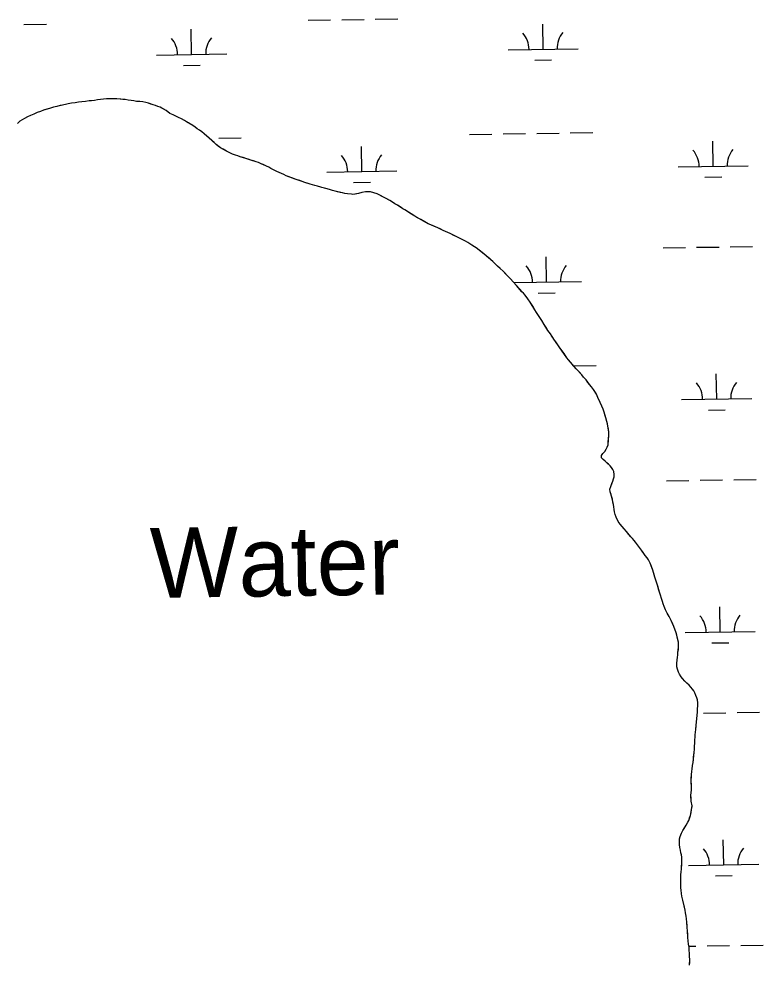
# Model space of a CAD drawing. Extents: x 3807117 to 3845308, y 337856 to 363736.
# Drawn here: x 3839396 to 3840459, y 351307 to 352657 of the extents above; entities that cross this region are included whole.
import ezdxf

# ---------------------------------------------------------------- set-up
doc = ezdxf.new("R2010")
doc.units = 0
for name, color, linetype in [('V-RIVR-IDEN', 7, 'Continuous'), ('V-TOPO-SHOR', 7, 'Continuous'), ('V-WETL-SWMP', 7, 'Continuous')]:
    doc.layers.add(name, color=color, linetype=linetype)

msp = doc.modelspace()

# ---------------------------------------------------------------- linework, layer by layer
at = {"layer": 'V-TOPO-SHOR'}
for points in [[(3839581.4, 352536.2), (3839577.6, 352537.3), (3839573.1, 352538.3), (3839569, 352538.6), (3839563.9, 352538.8), (3839560.5, 352539.5), (3839556.4, 352540.1), (3839552.1, 352540.8), (3839548.1, 352541.4), (3839544.6, 352541.7), (3839540.6, 352542.1), (3839535.9, 352542.6), (3839531, 352542.6), (3839525.9, 352542.7), (3839521.2, 352542.5), (3839516.9, 352542.1), (3839512.7, 352541.4), (3839508.6, 352541), (3839504.1, 352540.2), (3839499.8, 352539.8), (3839496.4, 352539.5), (3839491.3, 352538.9), (3839486.2, 352538.4), (3839481.5, 352537.8), (3839476.6, 352537), (3839471.5, 352536.4), (3839466.4, 352535.3), (3839462.7, 352534.5), (3839458.2, 352533.5), (3839455.2, 352532.9), (3839450.5, 352531.8), (3839445.8, 352530.6), (3839439.9, 352528.8), (3839436.2, 352527.8), (3839431.5, 352526.4), (3839426.8, 352524.5), (3839422.1, 352522.9), (3839417.4, 352520.9), (3839412.7, 352518.7), (3839408.6, 352517.1), (3839404.3, 352514.5), (3839400.9, 352512.7), (3839397.6, 352510.5), (3839394.1, 352507.3)], [(3839933.3, 352392.7), (3839929.7, 352395.1), (3839925.7, 352397.3), (3839921.5, 352399.7), (3839918.8, 352401.3), (3839915.1, 352403.2), (3839910.5, 352405.6), (3839907.6, 352406.9), (3839902.9, 352408.4), (3839898.3, 352409.5), (3839894.3, 352409.9), (3839891.1, 352409.6), (3839885.8, 352408.6), (3839881.2, 352407.3), (3839876.2, 352406.4), (3839873, 352405.9), (3839871.2, 352406.3), (3839865.5, 352406.8), (3839861.7, 352407.4), (3839858.4, 352408.1), (3839855.2, 352408.9), (3839851.3, 352409.9), (3839847.9, 352410.6), (3839844.2, 352411.6), (3839839.8, 352412.9), (3839836.5, 352413.8), (3839832.4, 352415), (3839829, 352416.1), (3839826, 352416.9), (3839822.5, 352417.8), (3839819, 352419), (3839815.6, 352419.9), (3839812.1, 352420.9), (3839807.9, 352422.2), (3839807.5, 352422.2), (3839804.4, 352423.2), (3839800.8, 352424.5), (3839797.5, 352425.7), (3839793.7, 352427), (3839790.8, 352428), (3839787.6, 352429.1), (3839784.6, 352430.3), (3839780.9, 352431.6), (3839777.7, 352432.8), (3839774.6, 352434.3), (3839771.2, 352435.7), (3839768.1, 352437.2), (3839764.7, 352438.9), (3839761.7, 352440.3), (3839759, 352441.8), (3839756.2, 352443.2), (3839752.9, 352445.1), (3839748.9, 352446.9), (3839745.2, 352448.6), (3839742, 352449.9), (3839738.4, 352451.7), (3839735.1, 352452.8), (3839731.3, 352454), (3839727.4, 352455.1), (3839723.5, 352456.5), (3839720.5, 352457.4), (3839716.6, 352458.6), (3839712.4, 352459.7), (3839708.9, 352461.1), (3839705.5, 352462), (3839701.2, 352463.7), (3839697.4, 352465.3), (3839692.5, 352467.8), (3839688, 352470.5), (3839684, 352472.8), (3839680.8, 352475.1), (3839677.9, 352477.5), (3839674.9, 352480.2), (3839671.7, 352483.1), (3839668.1, 352486.2), (3839664.4, 352489.3), (3839660.6, 352492.5), (3839657.3, 352495.4), (3839654.1, 352497.7), (3839650.7, 352499.8), (3839647.8, 352502), (3839644.6, 352504.7), (3839641.4, 352506.4), (3839638.3, 352508.2), (3839635.3, 352509.7), (3839632.5, 352511.5), (3839628.2, 352514), (3839624, 352515.9), (3839620.1, 352518), (3839616.3, 352519.8), (3839611.8, 352521.7), (3839609.2, 352523.6), (3839606.3, 352525.8), (3839603.1, 352527.7), (3839600.5, 352529.3), (3839597.8, 352530.6), (3839594.4, 352531.8), (3839591.4, 352532.9), (3839588.1, 352533.9), (3839584.7, 352535), (3839581.4, 352536.2)], [(3840230, 352036), (3840232.8, 352039), (3840235.1, 352042.1), (3840236.4, 352045.1), (3840237.6, 352048.5), (3840237.9, 352052.8), (3840238.3, 352057.5), (3840238.6, 352061.8), (3840238.8, 352066.6), (3840238.2, 352070.7), (3840237.5, 352074.8), (3840236.7, 352078.3), (3840235.7, 352081.5), (3840234.5, 352086.8), (3840233.1, 352091.3), (3840231.9, 352095.2), (3840230.4, 352099.1), (3840228.6, 352103.6), (3840226.4, 352108.9), (3840225, 352111.8), (3840223.2, 352115.8), (3840221.2, 352120.5), (3840219.6, 352123), (3840216.8, 352127.3), (3840214, 352131.2), (3840211.1, 352134.7), (3840208.9, 352137.4), (3840206.1, 352141), (3840202.3, 352145.2), (3840199.9, 352148.2), (3840196.1, 352152.5), (3840192.2, 352157.1), (3840188.4, 352161.4), (3840184.2, 352166.1), (3840181.1, 352169.8), (3840178.9, 352172.8), (3840174.7, 352178.8), (3840171.9, 352182.7), (3840168.9, 352187), (3840166.9, 352189.6), (3840163.9, 352193.9), (3840160.1, 352199.1), (3840158.5, 352201.7), (3840156.8, 352204.2), (3840155.2, 352206.7), (3840151.6, 352211.8), (3840150, 352214.4), (3840146.4, 352220.2), (3840143, 352226.1), (3840139.4, 352231.6), (3840135.6, 352237.6), (3840133.2, 352241.1), (3840130, 352246.2), (3840126.4, 352251.9), (3840123.1, 352257), (3840119.3, 352261.9), (3840116.7, 352264.8), (3840114.5, 352267.1), (3840111.7, 352270.2), (3840107, 352275.7), (3840102.2, 352281), (3840098.4, 352285.3), (3840095.8, 352287.8), (3840091.7, 352292.1), (3840087.7, 352296.2), (3840083.7, 352300.1), (3840079.8, 352303.4), (3840077.6, 352305.6), (3840072.8, 352310.1), (3840068.6, 352313.8), (3840063.6, 352318.3), (3840060.7, 352320.9), (3840055.2, 352325), (3840049.3, 352329.6), (3840046.8, 352331.4), (3840043.1, 352333.7), (3840037.2, 352337.2), (3840034, 352339.1), (3840029.2, 352341.6), (3840025.4, 352343.7), (3840020.6, 352346), (3840017.5, 352347.5), (3840011.9, 352350.3), (3840005.2, 352353.2), (3840002.3, 352354.7), (3839997.6, 352356.7), (3839994.3, 352358.1), (3839989.7, 352360.2), (3839984.3, 352362.7), (3839980.8, 352364.2), (3839975.7, 352367), (3839970.1, 352370.1), (3839964.7, 352373.1), (3839961.6, 352374.8), (3839956.9, 352377.8), (3839951.6, 352381.1), (3839947.4, 352383.8), (3839944.5, 352385.5), (3839940.5, 352388.1), (3839936.9, 352390.5), (3839933.3, 352392.7)], [(3840365.3, 351667.1), (3840365.3, 351671), (3840365.6, 351675.7), (3840365.6, 351679.8), (3840365.1, 351684), (3840364.3, 351687.1), (3840363.1, 351690.4), (3840361.5, 351694.1), (3840359.9, 351696.7), (3840358.1, 351699.2), (3840355.7, 351702), (3840353.4, 351704.9), (3840350.2, 351708), (3840347.4, 351710.9), (3840344, 351714.6), (3840342, 351717), (3840339.6, 351720.9), (3840338.2, 351723.8), (3840336.8, 351727.9), (3840336, 351731.3), (3840335.8, 351736.6), (3840336.1, 351740.5), (3840336.7, 351745), (3840337.2, 351748), (3840337.4, 351751.5), (3840338, 351755.5), (3840338.3, 351758.8), (3840338.3, 351763.3), (3840338.1, 351766.5), (3840336.8, 351771.8), (3840335.8, 351776.5), (3840335, 351779.6), (3840333.4, 351783.7), (3840331.4, 351789), (3840329, 351794.3), (3840327.6, 351797.4), (3840324.7, 351802.9), (3840321.8, 351808), (3840319.5, 351812.7), (3840317.7, 351817.6), (3840316.1, 351821.3), (3840315.3, 351824.3), (3840313.7, 351829), (3840312.5, 351833.7), (3840311.1, 351838), (3840309.8, 351842.3), (3840308.6, 351846.4), (3840307.2, 351850.7), (3840305.8, 351855), (3840304.6, 351859.4), (3840303, 351864.5), (3840301.3, 351869.5), (3840299.5, 351874.4), (3840297.5, 351879.5), (3840295.3, 351884.2), (3840293.5, 351886.8), (3840290.7, 351890.3), (3840287.7, 351894.4), (3840285.2, 351897.9), (3840282.6, 351901.6), (3840279.6, 351905.5), (3840276.8, 351909.2), (3840274.8, 351911.6), (3840272.4, 351914.7), (3840270.2, 351917), (3840266.9, 351920.9), (3840263.7, 351924.6), (3840260.5, 351928.5), (3840257.5, 351931.9), (3840254.9, 351934.8), (3840252.2, 351938.9), (3840250.7, 351941.8), (3840249.3, 351945), (3840247.7, 351948.9), (3840246.7, 351952.6), (3840246.3, 351956.3), (3840245.9, 351959.5), (3840245.4, 351963), (3840244.6, 351966.3), (3840243.8, 351970.5), (3840243, 351973.8), (3840242, 351977.3), (3840240.8, 351981.4), (3840240.3, 351985), (3840241.7, 351988.9), (3840243.2, 351992.9), (3840244.6, 351996.2), (3840245.5, 351999.6), (3840246.1, 352002.7), (3840246.2, 352005.9), (3840245.6, 352010), (3840244.2, 352013.3), (3840242.6, 352015.9), (3840240.4, 352018.2), (3840238, 352020.5), (3840235.9, 352022.7), (3840233.3, 352025), (3840230.7, 352027.2), (3840228.1, 352029.7), (3840228.1, 352033.2), (3840230, 352036)], [(3840354, 351305.2), (3840354.2, 351308.8), (3840354.4, 351313.1), (3840353.9, 351317.4), (3840353.7, 351321.9), (3840353.5, 351326.3), (3840353.2, 351330.8), (3840352.6, 351335.1), (3840352.1, 351340), (3840351.5, 351344.7), (3840351.3, 351349.2), (3840351, 351354), (3840350.6, 351358.7), (3840350.4, 351361.8), (3840350.1, 351366.5), (3840349.7, 351371.4), (3840349.3, 351375), (3840348.4, 351379.7), (3840347.6, 351383.6), (3840346.6, 351387.7), (3840345.6, 351392.2), (3840344.2, 351398.1), (3840343.1, 351403.4), (3840342.5, 351407.3), (3840341.9, 351412.3), (3840341.6, 351415.4), (3840341.6, 351421.5), (3840341.5, 351425.8), (3840341.7, 351430.5), (3840341.7, 351433.7), (3840342, 351438.6), (3840342.4, 351441.8), (3840342.7, 351446.1), (3840343.1, 351450.2), (3840343.1, 351454.3), (3840342.8, 351459.1), (3840342.4, 351462.4), (3840341.6, 351465.3), (3840341, 351469.1), (3840339.9, 351473.2), (3840339.5, 351477.5), (3840339.5, 351481.4), (3840339.8, 351485.6), (3840340.4, 351488.9), (3840342.3, 351493.6), (3840344.6, 351497.6), (3840346.4, 351500.4), (3840349.3, 351504.9), (3840351.6, 351509.1), (3840352.9, 351511.8), (3840354.1, 351515.4), (3840355.2, 351518.7), (3840356.2, 351523.3), (3840356.9, 351527.2), (3840357.5, 351531.3), (3840357.7, 351532.7), (3840356.4, 351539.2), (3840356.2, 351544.1), (3840356, 351547.4), (3840356.3, 351551.4), (3840356.7, 351555.5), (3840356.8, 351559.2), (3840356.6, 351564), (3840356.4, 351567.1), (3840356.5, 351571.6), (3840356.7, 351576.7), (3840357.2, 351582.1), (3840357.8, 351585), (3840358.3, 351590.1), (3840359.1, 351594.3), (3840359.4, 351598.2), (3840359.8, 351602.3), (3840360.2, 351605.7), (3840360.5, 351609.4), (3840361.1, 351613), (3840361.2, 351617.3), (3840361.4, 351622.6), (3840361.5, 351626.7), (3840361.9, 351630.7), (3840362.1, 351634.2), (3840362.4, 351638.1), (3840362.8, 351641.9), (3840363.5, 351647.8), (3840364.1, 351652.7), (3840364.4, 351656.8), (3840365, 351661.7), (3840365.3, 351667.1)]]:
    msp.add_lwpolyline(points, dxfattribs=at)
at = {"layer": 'V-WETL-SWMP'}
for p, q in [((3839403.4, 352648.8), (3839435.4, 352649.2)), ((3839809.2, 352654.9), (3839841.2, 352655.3)), ((3839857.2, 352655.6), (3839889.2, 352656)), ((3839905.2, 352656.3), (3839937.2, 352656.8)), ((3840144.7, 352613.4), (3840144.2, 352649.4)), ((3839642.9, 352605.9), (3839642.3, 352641.9)), ((3840094.7, 352612.7), (3840194.7, 352614.2)), ((3839592.9, 352605.2), (3839692.9, 352606.7)), ((3840133, 352597.8), (3840157, 352598.2)), ((3839631.1, 352590.3), (3839655.1, 352590.7)), ((3839681.8, 352486.4), (3839713.8, 352486.9)), ((3840039.7, 352491.8), (3840071.7, 352492.3)), ((3840087.7, 352492.5), (3840119.7, 352493)), ((3840135.7, 352493.2), (3840167.7, 352493.7)), ((3840183.7, 352493.9), (3840215.7, 352494.4)), ((3839885.9, 352438.7), (3839885.3, 352474.7)), ((3840387.7, 352446.2), (3840387.2, 352482.2)), ((3840337.7, 352445.5), (3840437.7, 352447)), ((3839835.9, 352438), (3839935.9, 352439.5)), ((3839874.1, 352423.1), (3839898.1, 352423.5)), ((3840376, 352430.6), (3840400, 352431)), ((3840316.1, 352329.7), (3840348.1, 352330.2)), ((3840364.1, 352330.5), (3840396.1, 352330.9)), ((3840412.1, 352331.2), (3840444, 352331.6)), ((3840149.7, 352280.8), (3840149.2, 352316.8)), ((3840103, 352280.1), (3840199.7, 352281.6)), ((3840137.9, 352265.2), (3840161.9, 352265.6)), ((3840188.7, 352161.3), (3840220.7, 352161.8)), ((3840392.7, 352113.6), (3840392.2, 352149.6)), ((3840342.7, 352112.9), (3840442.7, 352114.4)), ((3840380.9, 352098), (3840404.9, 352098.4)), ((3840321, 351997.1), (3840353, 351997.6)), ((3840369, 351997.8), (3840401, 351998.3)), ((3840417, 351998.5), (3840449, 351999)), ((3840397.7, 351781), (3840397.2, 351817)), ((3840347.7, 351780.2), (3840447.7, 351781.7)), ((3840385.9, 351765.4), (3840409.9, 351765.7)), ((3840374, 351665.2), (3840406, 351665.7)), ((3840422, 351665.9), (3840454, 351666.4)), ((3840402.7, 351448.3), (3840402.1, 351484.3)), ((3840352.7, 351447.6), (3840452.7, 351449.1)), ((3840390.9, 351432.7), (3840414.9, 351433.1)), ((3840353, 351332.1), (3840363, 351332.3)), ((3840379, 351332.5), (3840411, 351333)), ((3840427, 351333.3), (3840459, 351333.7))]:
    msp.add_line(p, q, dxfattribs=at)
for points in [[(3839581.4, 352536.2), (3839577.6, 352537.3), (3839573.1, 352538.3), (3839569, 352538.6), (3839563.9, 352538.8), (3839560.5, 352539.5), (3839556.4, 352540.1), (3839552.1, 352540.8), (3839548.1, 352541.4), (3839535.9, 352542.6), (3839531, 352542.6), (3839525.9, 352542.7), (3839521.2, 352542.5), (3839516.9, 352542.1), (3839512.7, 352541.4), (3839508.6, 352541), (3839504.1, 352540.2), (3839496.4, 352539.5), (3839491.3, 352538.9), (3839486.2, 352538.4), (3839481.5, 352537.8), (3839476.6, 352537), (3839471.5, 352536.4), (3839466.4, 352535.3), (3839450.5, 352531.8), (3839445.8, 352530.6), (3839439.9, 352528.8), (3839431.5, 352526.4), (3839426.8, 352524.5), (3839422.1, 352522.9), (3839417.4, 352520.9), (3839412.7, 352518.7), (3839408.6, 352517.1), (3839404.3, 352514.5), (3839400.9, 352512.7), (3839397.6, 352510.5), (3839394.1, 352507.3)], [(3840135.6, 352237.6), (3840133.2, 352241.1), (3840126.4, 352251.9), (3840123.1, 352257), (3840119.3, 352261.9), (3840098.4, 352285.3), (3840095.8, 352287.8), (3840087.7, 352296.2), (3840083.7, 352300.1), (3840079.8, 352303.4), (3840077.6, 352305.6), (3840072.8, 352310.1), (3840060.7, 352320.9), (3840049.3, 352329.6), (3840046.8, 352331.4), (3840043.1, 352333.7), (3840037.2, 352337.2), (3840034, 352339.1), (3840025.4, 352343.7), (3840020.6, 352346), (3840011.9, 352350.3), (3840005.2, 352353.2), (3840002.3, 352354.7), (3839994.3, 352358.1), (3839984.3, 352362.7), (3839980.8, 352364.2), (3839961.6, 352374.8), (3839947.4, 352383.8), (3839944.5, 352385.5), (3839936.9, 352390.5), (3839933.3, 352392.7), (3839929.7, 352395.1), (3839925.7, 352397.3), (3839918.8, 352401.3), (3839910.5, 352405.6), (3839907.6, 352406.9), (3839902.9, 352408.4), (3839898.3, 352409.5), (3839894.3, 352409.9), (3839891.1, 352409.6), (3839885.8, 352408.6), (3839881.2, 352407.3), (3839873, 352405.9), (3839871.2, 352406.3), (3839865.5, 352406.8), (3839861.7, 352407.4), (3839844.2, 352411.6), (3839839.8, 352412.9), (3839832.4, 352415), (3839829, 352416.1), (3839822.5, 352417.8), (3839819, 352419), (3839812.1, 352420.9), (3839807.9, 352422.2), (3839807.5, 352422.2), (3839804.4, 352423.2), (3839800.8, 352424.5), (3839790.8, 352428), (3839777.7, 352432.8), (3839774.6, 352434.3), (3839771.2, 352435.7), (3839764.7, 352438.9), (3839761.7, 352440.3), (3839759, 352441.8), (3839756.2, 352443.2), (3839752.9, 352445.1), (3839742, 352449.9), (3839738.4, 352451.7), (3839735.1, 352452.8), (3839727.4, 352455.1), (3839720.5, 352457.4), (3839712.4, 352459.7), (3839708.9, 352461), (3839705.5, 352462), (3839701.2, 352463.7), (3839697.4, 352465.3), (3839692.5, 352467.8), (3839684, 352472.8), (3839677.9, 352477.5), (3839671.7, 352483.1), (3839668.1, 352486.2), (3839660.6, 352492.5), (3839657.3, 352495.4), (3839654.1, 352497.7), (3839650.7, 352499.8), (3839647.8, 352502), (3839644.6, 352504.7), (3839635.3, 352509.7), (3839632.5, 352511.5), (3839628.2, 352514), (3839624, 352515.9), (3839620.1, 352518), (3839616.3, 352519.8), (3839611.8, 352521.7), (3839606.3, 352525.8), (3839600.5, 352529.3), (3839597.8, 352530.6), (3839594.4, 352531.8), (3839591.4, 352532.9), (3839588.1, 352533.9), (3839581.4, 352536.2)], [(3840347.4, 351710.9), (3840344, 351714.6), (3840342, 351717), (3840339.6, 351720.9), (3840338.2, 351723.8), (3840336.8, 351727.9), (3840336, 351731.3), (3840335.8, 351736.6), (3840336.1, 351740.5), (3840336.7, 351745), (3840337.2, 351748), (3840337.4, 351751.5), (3840338.3, 351758.8), (3840338.3, 351763.3), (3840338.1, 351766.5), (3840335.8, 351776.5), (3840335, 351779.6), (3840331.4, 351789), (3840327.6, 351797.4), (3840324.7, 351802.9), (3840321.8, 351808), (3840319.5, 351812.7), (3840317.7, 351817.6), (3840316.1, 351821.3), (3840315.3, 351824.3), (3840313.7, 351829), (3840312.5, 351833.7), (3840311.1, 351838), (3840308.6, 351846.4), (3840305.8, 351855), (3840304.6, 351859.4), (3840301.3, 351869.5), (3840297.5, 351879.5), (3840295.3, 351884.2), (3840293.5, 351886.8), (3840290.7, 351890.3), (3840285.2, 351897.9), (3840282.6, 351901.6), (3840276.8, 351909.2), (3840274.8, 351911.6), (3840272.4, 351914.7), (3840270.2, 351917), (3840263.7, 351924.6), (3840260.5, 351928.5), (3840254.9, 351934.8), (3840252.2, 351938.9), (3840249.3, 351945), (3840247.7, 351948.9), (3840246.7, 351952.6), (3840245.4, 351963), (3840243, 351973.8), (3840240.8, 351981.4), (3840240.3, 351985), (3840241.7, 351988.9), (3840244.6, 351996.2), (3840245.5, 351999.6), (3840246.1, 352002.7), (3840246.2, 352005.9), (3840245.6, 352010), (3840244.2, 352013.3), (3840242.6, 352015.9), (3840240.4, 352018.2), (3840235.9, 352022.7), (3840233.3, 352025), (3840230.7, 352027.2), (3840228.1, 352029.7), (3840228.1, 352033.2), (3840230, 352036), (3840232.8, 352039), (3840235.1, 352042.1), (3840236.4, 352045.1), (3840237.6, 352048.5), (3840238.6, 352061.8), (3840238.8, 352066.6), (3840237.5, 352074.8), (3840236.7, 352078.3), (3840235.7, 352081.5), (3840234.5, 352086.8), (3840231.9, 352095.2), (3840230.4, 352099.1), (3840226.4, 352108.9), (3840223.2, 352115.8), (3840221.2, 352120.5), (3840216.8, 352127.3), (3840214, 352131.2), (3840211.1, 352134.7), (3840206.1, 352141), (3840202.3, 352145.2), (3840199.9, 352148.2), (3840192.2, 352157.1), (3840181.1, 352169.8), (3840178.9, 352172.8), (3840168.9, 352187), (3840166.9, 352189.6), (3840160.1, 352199.1), (3840155.2, 352206.7), (3840151.6, 352211.8), (3840146.4, 352220.2), (3840143, 352226.1), (3840139.4, 352231.6), (3840135.6, 352237.6)], [(3840354, 351305.2), (3840354.4, 351313.1), (3840353.9, 351317.4), (3840353.2, 351330.8), (3840352.6, 351335.1), (3840352.1, 351340), (3840351.5, 351344.7), (3840351, 351354), (3840350.6, 351358.7), (3840350.1, 351366.5), (3840349.7, 351371.4), (3840349.3, 351375), (3840348.4, 351379.7), (3840347.6, 351383.6), (3840344.2, 351398.1), (3840343.1, 351403.4), (3840342.5, 351407.3), (3840341.9, 351412.3), (3840341.6, 351415.4), (3840341.5, 351425.8), (3840341.7, 351430.5), (3840341.7, 351433.7), (3840342, 351438.6), (3840342.4, 351441.8), (3840343.1, 351450.2), (3840343.1, 351454.3), (3840342.8, 351459.1), (3840342.4, 351462.4), (3840341.6, 351465.3), (3840341, 351469.1), (3840339.9, 351473.2), (3840339.5, 351477.5), (3840339.5, 351481.4), (3840339.8, 351485.6), (3840340.4, 351488.9), (3840342.3, 351493.6), (3840344.6, 351497.6), (3840349.3, 351504.9), (3840351.6, 351509.1), (3840352.9, 351511.8), (3840355.2, 351518.7), (3840356.9, 351527.2), (3840357.7, 351532.7), (3840356.4, 351539.2), (3840356, 351547.4), (3840356.7, 351555.5), (3840356.8, 351559.2), (3840356.4, 351567.1), (3840356.7, 351576.7), (3840357.2, 351582.1), (3840357.8, 351585), (3840358.3, 351590.1), (3840359.1, 351594.3), (3840360.5, 351609.4), (3840361.1, 351613), (3840361.5, 351626.7), (3840361.9, 351630.7), (3840362.1, 351634.2), (3840362.8, 351641.9), (3840364.1, 351652.7), (3840365, 351661.7), (3840365.3, 351667.1), (3840365.3, 351671), (3840365.6, 351675.7), (3840365.6, 351679.8), (3840365.1, 351684), (3840364.3, 351687.1), (3840363.1, 351690.4), (3840361.5, 351694.1), (3840359.9, 351696.7), (3840358.1, 351699.2), (3840353.4, 351704.9), (3840350.2, 351708), (3840347.4, 351710.9)]]:
    msp.add_lwpolyline(points, dxfattribs=at)
for centre, start, end in [((3840089.5, 352613.1), 0.0865, 41.6302), ((3840200, 352614.7), 140.0865, 181.6302), ((3839587.6, 352605.6), 0.0865, 41.6302), ((3839698.1, 352607.2), 140.0865, 181.6302), ((3839830.6, 352438.4), 0.0865, 41.6302), ((3839941.1, 352440), 140.0865, 181.6302), ((3840332.5, 352445.9), 0.0865, 41.6302), ((3840443, 352447.6), 140.0865, 181.6302), ((3840094.5, 352280.5), 0.0865, 41.6302), ((3840204.9, 352282.1), 140.0865, 181.6302), ((3840337.5, 352113.3), 0.0865, 41.6302), ((3840447.9, 352114.9), 140.0865, 181.6302), ((3840342.5, 351780.6), 0.0865, 41.6302), ((3840452.9, 351782.3), 140.0865, 181.6302), ((3840347.4, 351448), 0.0865, 41.6302), ((3840457.9, 351449.6), 140.0865, 181.6302)]:
    msp.add_arc(centre, 35.2, start, end, dxfattribs=at)

# ---------------------------------------------------------------- texts
at = {"layer": 'V-RIVR-IDEN'}
msp.add_text('Water', height=100, rotation=0.8756, dxfattribs=at).set_placement((3839584.2, 351829.4))

doc.saveas('drawing.dxf')
